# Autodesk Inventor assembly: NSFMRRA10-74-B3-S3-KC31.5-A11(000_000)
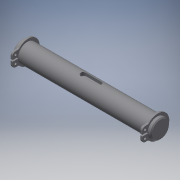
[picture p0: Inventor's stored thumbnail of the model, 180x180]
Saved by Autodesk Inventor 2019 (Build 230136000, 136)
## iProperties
Category: PARTsolutions
Company: MISUMI
Created: 2022-11
Part Number: NSFMRRA10-74-B3-S3-KC31.5-A11(000_000)
Catalog Web Link: www.cadenas.de
Description: NSFMRR, SFMRR, PSFMRR, SSFMRR, NSFHRR, SFHRR, PSFHRR, SSFHRR, NSFRR, SFRR, PSFRR, SSFRR, NSFMRRA, SFMRRA, PSFMRRA, SSFMRRA, NSFHRRA, SFHRRA, PSFHRRA, SSFHRRA, N
Vendor: MISUMI
Document SubType Name: Assembly
Designer: psAdmin
Manufacturer: MISUMI
Mass: 5.85506 g
Surface Area: 29.329 cm^2
Volume: 5.85506 cm^3
Density: 1 g/cm^3
Title: NSFMRRA10-74-B3-S3-KC31.5-A11
Author: Cadenas PARTsolutions
Comments: Rotary Shafts - Retaining Ring Grooves on Both Ends - Standard
PSOL_IDENT_0: {$CADENAS_DATA/23d-libs/misumi/metric/11_rotary_shafts/psfrra_asmtab.prj},820 {VTYP=3D},{STYP=ASSTAB
PSOL_IDENT_1: },{NB=NSFMRRA10-74-B3-S3-KC31.5-A11(000_000)},{LINA=NSFMRRA10-74-B3-S3-KC31.5-A11},{NN=NSFMRR, SFMRR
PSOL_IDENT_2: , PSFMRR, SSFMRR, NSFHRR, SFHRR, PSFHRR, SSFHRR, NSFRR, SFRR, PSFRR, SSFRR, NSFMRRA, SFMRRA, PSFMRRA
PSOL_IDENT_3: , SSFMRRA, NSFHRRA, SFHRRA, PSFHRRA, SSFHRRA, NSFRRA, SFRRA, PSFRRA, SSFRRA, HFRRA, PHFRRA, PSFRR PS
PSOL_IDENT_4: FRRA, PSFHRR, PSFHRRA, SSFRR, SSFRRA, SSFHRR, SSFHRRA, PPSFRR, PPSFRRA, PPSFHRR, PPSFHRRA, SSSFRR, S
PSOL_IDENT_5: SSFRRA, SSSFHRR, SSSFHRRA_shaft},{DATE=21.04.2022 07:40:19},{GEOMDATE=27.07.2021 08:15:02},{VERSION=
PSOL_IDENT_6: },{LINEID=30},{WBVAR=TS,TYS,MAT,ST,ALT1,L,B,S,ALT2,KC,A,WKC,C,K,E,KZ,Z,ALT3,FC,GALT3,WFC,J,WALT3,V,A
PSOL_IDENT_7: LT4,SFC,SG,AG,ALT5,UC,ALT7,SC,ALT10,KWC,ALT11,WC,ALT32,CD,ALT34,TCJ,WTCJ,XT,HCJ,WHCJ,XH},{WBNUMERIC=
PSOL_IDENT_8: L,B,S,KC,A,WKC,C,K,E,KZ,Z,FC,GALT3,WFC,J,WALT3,V,SFC,SG,AG,UC,SC,KWC,WC,TCJ,WTCJ,XT,HCJ,WHCJ,XH}  {N
PSOL_IDENT_9: B=NSFMRRA10-74-B3-S3-KC31.5-A11(000_000)},{LINA=NSFMRRA10-74-B3-S3-KC31.5-A11},{KT=DUMMY},{PN=NSFMRR
PSOL_IDENT_10: A10-74-B3-S3-KC31.5-A11},{TYPE=NSFMRRA},{TS=SWR},{TYS=H9},{TYSALG= 'H9','h9 (Cold-drawn)','H7','h7 (
PSOL_IDENT_11: Ground)','G6','g6 (Ground)' },{MAT=S45C},{MATALG= 'S45C','S45C Equivalent', 'SUS304','SUS304' },{ST=
PSOL_IDENT_12: },{STALG= '','-','BO','Black Oxide', 'ENP','Electroless Nickel Plating' },{D=10.0},{ALT1=},{ALT1ALG=
PSOL_IDENT_13: '','w/o LKC (Changes L Tolerance)','-LKC','with LKC (Changes L Tolerance)' },{L=74.0},{LALG=[15:800
PSOL_IDENT_14: /0.1]},{LMIN=15},{LMAX=800},{NOTE=25},{B=3.0},{BALG=[3:70/0.1]},{BMAX=70},{S=3.0},{SALG=[3:69/0.1]},
PSOL_IDENT_15: {SMAX=69},{MM=1.15},{DD=9.6},{ARR=STWS10},{ALT2=KC},{ALT2ALG= '', 'w/o Key Grooves','KC','with KC (K
PSOL_IDENT_16: ey Groove)','WKC','with WKC (Two Key Grooves)','KCWKC','with KC + WKC (Three Key Grooves)','KZ','wit
PSOL_IDENT_17: h KC + WKC + KZ (Four Key Grooves)' },{ALT2PN=-KC31.5-A11},{KC=31.5},{KCALG=[0:71/0.1]},{KCMIN=0},{K
PSOL_IDENT_18: CMAX=71},{A=11.0},{AALG=[3:42.5/0.1]},{AMIN=3},{AMAX=42.5},{WKC=0.0},{WKCALG=[0]},{WKCMIN=0},{WKCMAX=
PSOL_IDENT_19: 0},{C=0.0},{CALG=[0]},{CMIN=3},{CMAX=0},{K=0.0},{KALG=[0]},{KMIN=0},{KMAX=69},{E=0.0},{EALG=[0]},{EM
PSOL_IDENT_20: IN=3},{EMAX=72},{KZ=0.0},{KZALG=[0]},{KZMIN=76},{KZMAX=71},{Z=0.0},{ZALG=[0]},{ZMIN=3},{ZMAX=74},{CI
PSOL_IDENT_21: FKC=2},{CIFWKC=1},{CIFK=1},{CIFKZ=2},{PCUT3D=0},{QCUT3D=0},{BB=3},{BBALT2=3},{TT=1.8},{TTALT2=1.8},{
PSOL_IDENT_22: ALT3=},{ALT3ALG= '', 'w/o Set Screw Flat','FC','with FC (Adds a Set Screw Flat)','WFC','with WFC (Ad
PSOL_IDENT_23: ds Two Set Screw Flats)','FCWFC','with FC + WFC (Adds Three Set Screw Flats)' },{ALT3PN=},{FC=0},{FC
PSOL_IDENT_24: ALG=[0]},{FCMIN=0},{FCMAX=73},{GALT3=0},{GALT3ALG=[0]},{GALT3MIN=1},{GALT3MAX=70},{GALT3MAX2=68},{GA
PSOL_IDENT_25: LT3MAX3=70},{WFC=0},{WFCALG=[0]},{WFCMIN=0},{WFCMIN2=2},{WFCMAX=70},{WFCMAX2=-3},{WFCMAX3=-4},{J=0},
PSOL_IDENT_26: {JALG=[0]},{JMIN=1},{JMAX=70},{JMAX2=-2},{JMAX3=-5},{WALT3=0},{WALT3ALG=[0]},{WALT3MIN=0},{WALT3MIN2=
PSOL_IDENT_27: 76},{WALT3MAX=71},{WALT3MAX2=71},{V=0},{VALG=[0]},{VMIN=1},{VMAX=70},{VMAX2=70},{CIFFC=0},{H=0},{ALT
PSOL_IDENT_28: 4=},{ALT4ALG= '', 'w/o SFC (2 Set Screw Flats (Angle Specified))', 'SFC'  , 'with SFC (2 Set Screw F
PSOL_IDENT_29: lats (Angle Specified))'},{ALT4PN=},{SFC=0},{SFCALG=[0]},{SFCMIN=0},{SFCMAX=73},{SG=0},{SGALG=[0]},{
PSOL_IDENT_30: SGMIN=1},{SGMAX=70},{AG=0},{AGALG=[0]},{CIFSFC=0},{ALT5=},{ALT5ALG= '', 'w/o UC (Slit Cam Groove)', '
PSOL_IDENT_31: UC', 'with UC (Slit Cam Groove)'},{ALT5PN=},{UC=0},{UCALG=[0]},{UCMIN=1},{UCMAX=68},{DDALT5=8},{LL1=
PSOL_IDENT_32: 0},{ALT7=},{ALT7ALG= '', 'w/o SC (Wrench Flats)', 'SC', 'with SC (Wrench Flats)'},{ALT7PN=},{SC=0},{
PSOL_IDENT_33: SCALG=[0]},{SCMIN=0},{SCMAX=74},{WALT7=0},{LL2=0},{CIFSC=0},{ALT10=},{ALT10ALG= '','Not applicable'
PSOL_IDENT_34: },{ALT10PN=},{KWC=0},{KWCALG=[0]},{KWCMIN=1},{KWCMAX=0},{WALT10=8},{ALT11=},{ALT11ALG= '','Not appli
PSOL_IDENT_35: cable' },{ALT11PN=},{WC=0.0},{WCALG=[0]},{ALT32=},{ALT32ALG=  '','w/o CD (Changes Part D Chamfering)'
PSOL_IDENT_36: ,'-CD', 'with CD (Changes Part D Chamfering)' },{CD=},{CDALG= '','N/A' },{CD3D=0.5},{CIF32=0},{CIF32
PSOL_IDENT_37: 0=0},{CIF32B=0},{CIF32S=0},{ALT32PN=},{ERRORPN=},{ERRORRALT2=OK},{ERRORRALT3=OK},{ERRORRALT4=NG},{ER
PSOL_IDENT_38: RORRALT5=NG},{ERRORRALT7=NG},{ERRORRALT10=OK},{ERRORALT23=OK},{ERRORALT24=OK},{ERRORALT25=OK},{ERROR
PSOL_IDENT_39: ALT27=OK},{ERRORALT210=OK},{ERRORALT34=OK},{ERRORALT35=OK},{ERRORALT37=OK},{ERRORALT310=OK},{ERRORAL
PSOL_IDENT_40: T45=OK},{ERRORALT47=OK},{ERRORALT410=OK},{ERRORALT75=OK},{ERRORALT510=OK},{ERRORALT710=OK},{ALT34=},
PSOL_IDENT_41: {ALT34ALG= '','Not applicable'},{TCJ=0},{WTCJ=0},{XT=0},{TM=4},{TCJALG=[0]},{TCJMIN=7.000},{TCJMAX=3
PSOL_IDENT_42: 4.000},{TCJMAX1=34.000},{HCJ=0},{WHCJ=0},{XH=0},{HP=4},{HCJALG=[0]},{HCJMIN=7.000},{HCJMAX=34.000},{
PSOL_IDENT_43: HCJMAX1=34.000},{LCJ=0},{LMINX=15},{XALG=[0]},{XCJMIN=7},{PPATH=11_components/psfrra/psfrra_asmtpl.p
PSOL_IDENT_44: rj},{WHCJALG=[0]},{WTCJALG=[0]},{XHALG=[0]}
NB: NSFMRRA10-74-B3-S3-KC31.5-A11(000_000)
NN: NSFMRR, SFMRR, PSFMRR, SSFMRR, NSFHRR, SFHRR, PSFHRR, SSFHRR, NSFRR, SFRR, PSFRR, SSFRR, NSFMRRA, SFMRRA, PSFMRRA, SSFMRRA, NSFHRRA, SFHRRA, PSFHRRA, SSFHRRA, N
NT: Rotary Shafts - Retaining Ring Grooves on Both Ends - Standard
NBSYN: $PN.($ALT34.$TCJ.$WTCJ.$XT._$HCJ.$WHCJ.$XH.)
LINA: NSFMRRA10-74-B3-S3-KC31.5-A11
CATALOG: Misumi
PN: NSFMRRA10-74-B3-S3-KC31.5-A11
TS: With Retaining Ring
TYS: h9 (Cold-drawn)
MAT: S45C Equivalent
ST: -
D: 10
ALT1: w/o LKC (Changes L Tolerance)
L: 74
B: 3
S: 3
MM: 1.15
DD: 9.6
ALT2: with KC (Key Groove)
KC: 31.5
A: 11
WKC: 0
C: 0
K: 0
E: 0
KZ: 0
Z: 0
ALT3: w/o Set Screw Flat
FC: 0
GALT3: 0
WFC: 0
J: 0
WALT3: 0
V: 0
ALT4: w/o SFC (2 Set Screw Flats (Angle Specified))
SFC: 0
SG: 0
AG: 0
ALT5: w/o UC (Slit Cam Groove)
UC: 0
ALT7: w/o SC (Wrench Flats)
SC: 0
ALT10: Not applicable
KWC: 0
ALT11: Not applicable
WC: 0
ALT32: w/o CD (Changes Part D Chamfering)
CD: N/A
ALT34: Not applicable
TCJ: 0
WTCJ: 0
XT: 0
HCJ: 0
WHCJ: 0
XH: 0
SUPPLIER: MISUMI
ARTICLENO: NSFMRRA10-74-B3-S3-KC31.5-A11(000_000)
BOMINFO: NSFMRRA10-74-B3-S3-KC31.5-A11
CREATOR: CADENAS GmbH
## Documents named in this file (3)
- e:\temp\worker_COMMON_8\temp\tmp_7620_202_2Xz7J\format_0\NSFMRRA10-74-B3-S3-KC31_5-A11(000_000).iam
- e:\temp\worker_COMMON_8\temp\tmp_7620_202_2Xz7J\format_0\NSFMRRA10-74-B3-S3-KC31_5-A11(000_000)_s.ipt
- e:\temp\worker_COMMON_8\temp\tmp_7620_202_2Xz7J\format_0\STWN10.ipt
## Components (3 placed, 2 different names)
1. NSFMRRA10-74-B3-S3-KC31_5-A11(000_000)_s:1 — to_ring_b_XY@1 <-> 1_XY@2, to_ring_b_Z@1 <-> 1_Z@2, to_ring_b_YZ@1 <-> 1_YZ@2, to_ring_s_XY@1 <-> 1_XY@3, to_ring_s_Z@1 <-> 1_Z@3, to_ring_s_YZ@1 <-> 1_YZ@3
2. STWN10:1 — to_ring_b_XY@1 <-> 1_XY@2, to_ring_b_Z@1 <-> 1_Z@2, to_ring_b_YZ@1 <-> 1_YZ@2
3. STWN10:2 — to_ring_s_XY@1 <-> 1_XY@3, to_ring_s_Z@1 <-> 1_Z@3, to_ring_s_YZ@1 <-> 1_YZ@3
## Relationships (6: Mate 3, Angle 2, Flush 1)
- to_ring_b_XY@1 <-> 1_XY@2 [Mate]: NSFMRRA10-74-B3-S3-KC31_5-A11(000_000)_s:1 ↔ STWN10:1
- to_ring_b_Z@1 <-> 1_Z@2 [Mate]: NSFMRRA10-74-B3-S3-KC31_5-A11(000_000)_s:1 ↔ STWN10:1
- to_ring_b_YZ@1 <-> 1_YZ@2 [Angle]: NSFMRRA10-74-B3-S3-KC31_5-A11(000_000)_s:1 ↔ STWN10:1
- to_ring_s_XY@1 <-> 1_XY@3 [Flush]: NSFMRRA10-74-B3-S3-KC31_5-A11(000_000)_s:1 ↔ STWN10:2
- to_ring_s_Z@1 <-> 1_Z@3 [Mate]: NSFMRRA10-74-B3-S3-KC31_5-A11(000_000)_s:1 ↔ STWN10:2
- to_ring_s_YZ@1 <-> 1_YZ@3 [Angle]: NSFMRRA10-74-B3-S3-KC31_5-A11(000_000)_s:1 ↔ STWN10:2
